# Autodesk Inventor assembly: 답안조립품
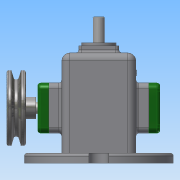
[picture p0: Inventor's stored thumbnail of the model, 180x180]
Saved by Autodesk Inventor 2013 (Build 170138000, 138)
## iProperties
Created: 2018-07
Part Number: 답안조립품
Document SubType Name: Assembly
Designer: Administrator
Author: Administrator
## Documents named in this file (16)
- C:\Users\Administrator\Desktop\480708V1009\답안조립품.iam
- C:\Users\Administrator\Desktop\480708V1009\본체.ipt
- C:\Users\Administrator\Desktop\480708V1009\V벨트풀리.ipt
- C:\Users\Administrator\Desktop\480708V1009\고정핀 1.2x8.ipt
- C:\Users\Administrator\Desktop\480708V1009\뒤커버.ipt
- C:\Users\Administrator\Desktop\480708V1009\링크.ipt
- C:\Users\Administrator\Desktop\480708V1009\멈춤나사 M3x8.ipt
- C:\Users\Administrator\Desktop\480708V1009\베어링 12x32x10.ipt
- C:\Users\Administrator\Desktop\480708V1009\볼트 M4.ipt
- C:\Users\Administrator\Desktop\480708V1009\부시.ipt
- C:\Users\Administrator\Desktop\480708V1009\슬라이드.ipt
- C:\Users\Administrator\Desktop\480708V1009\앞커버.ipt
- C:\Users\Administrator\Desktop\480708V1009\오일 실 12 25 7.ipt
- C:\Users\Administrator\Desktop\480708V1009\키 4x4x10.ipt
- C:\Users\Administrator\Desktop\480708V1009\편심축.ipt
- C:\Users\Administrator\Desktop\480708V1009\핀 5x18.ipt
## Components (3 placed, 3 different names)
1. V벨트풀리:1 — 플러쉬:1
2. 고정핀 1.2x8:1
3. 핀 5x18:1
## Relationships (1: Flush 1)
- 플러쉬:1 [Flush]: V벨트풀리:1
